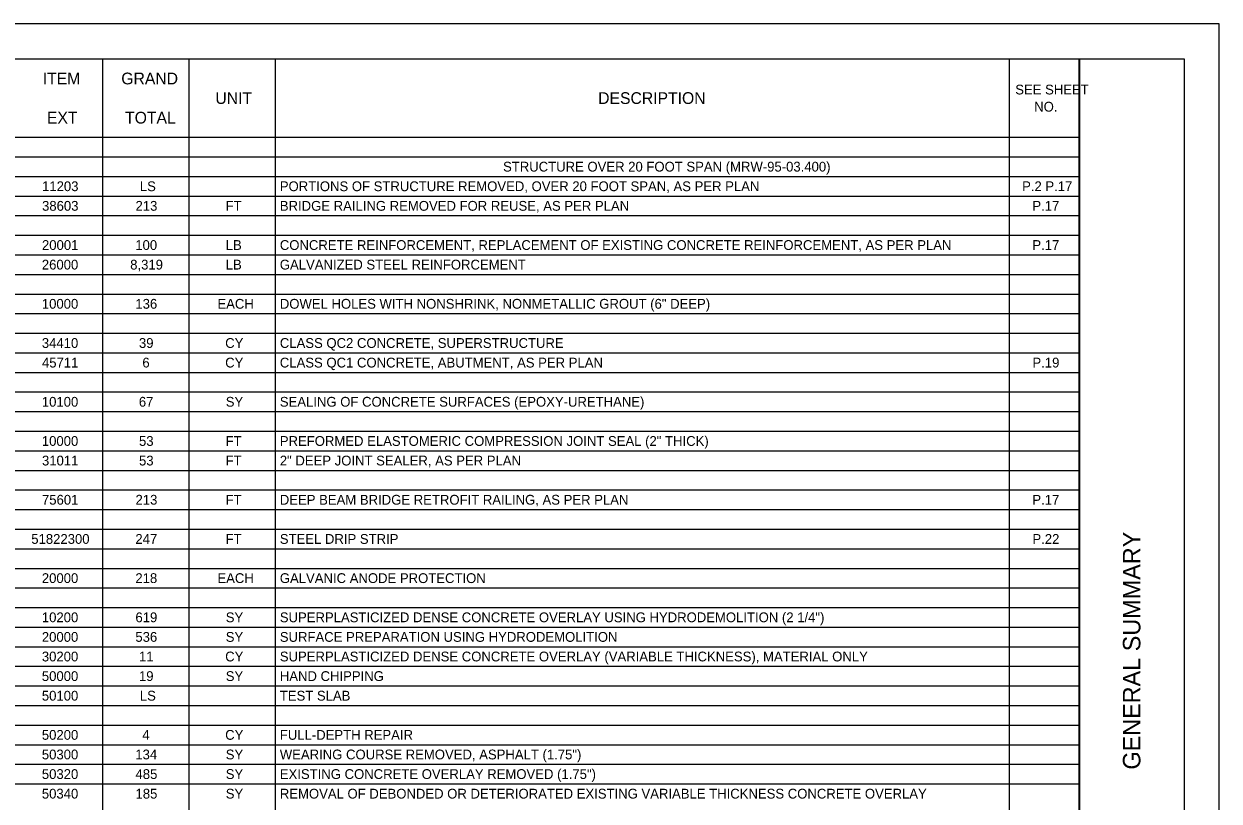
# Model space of a CAD drawing. Extents: x 0 to 34, y 0 to 22.
# Drawn here: x 16.91 to 34, y 10.89 to 22 of the extents above; entities that cross this region are included whole.
import ezdxf

# ---------------------------------------------------------------- set-up
doc = ezdxf.new("R2010")
doc.units = 0
for name, color, linetype in [('Default', 7, 'Continuous'), ('SH_Border', 7, 'Continuous'), ('SH_Cut_Line', 7, 'Continuous'), ('SH_Data', 7, 'Continuous')]:
    doc.layers.add(name, color=color, linetype=linetype)

msp = doc.modelspace()

# ---------------------------------------------------------------- linework, layer by layer
at = {"layer": 'SH_Border'}
msp.add_line((32, 0.5), (32, 21.5), dxfattribs=at)
msp.add_lwpolyline([(1.5, 21.5), (33.5, 21.5), (33.5, 0.5), (1.5, 0.5)], close=True, dxfattribs=at)
at = {"layer": 'SH_Cut_Line'}
msp.add_lwpolyline([(0, 0), (34, 0), (34, 22), (0, 22)], close=True, dxfattribs=at)
at = {"layer": 'SH_Data'}
for p, q in [((1.5, 21.5), (32.004, 21.5)), ((18.036, 21.5), (18.036, 0.5)), ((19.272, 21.5), (19.272, 0.5)), ((20.507, 21.5), (20.507, 0.5)), ((30.999, 21.5), (30.999, 0.5)), ((32.004, 21.5), (32.004, 0.5)), ((1.5, 20.38), (32.004, 20.38)), ((1.5, 20.1), (32.004, 20.1)), ((1.5, 19.82), (32.004, 19.82)), ((1.5, 19.54), (32.004, 19.54)), ((1.5, 19.26), (32.004, 19.26)), ((1.5, 18.98), (32.004, 18.98)), ((1.5, 18.7), (32.004, 18.7)), ((1.5, 18.42), (32.004, 18.42)), ((1.5, 18.14), (32.004, 18.14)), ((1.5, 17.86), (32.004, 17.86)), ((1.5, 17.58), (32.004, 17.58)), ((1.5, 17.3), (32.004, 17.3)), ((1.5, 17.02), (32.004, 17.02)), ((1.5, 16.74), (32.004, 16.74)), ((1.5, 16.46), (32.004, 16.46)), ((1.5, 16.18), (32.004, 16.18)), ((1.5, 15.9), (32.004, 15.9)), ((1.5, 15.62), (32.004, 15.62)), ((1.5, 15.34), (32.004, 15.34)), ((1.5, 15.06), (32.004, 15.06)), ((1.5, 14.78), (32.004, 14.78)), ((1.5, 14.5), (32.004, 14.5)), ((1.5, 14.22), (32.004, 14.22)), ((1.5, 13.94), (32.004, 13.94)), ((1.5, 13.66), (32.004, 13.66)), ((1.5, 13.38), (32.004, 13.38)), ((1.5, 13.1), (32.004, 13.1)), ((1.5, 12.82), (32.004, 12.82)), ((1.5, 12.54), (32.004, 12.54)), ((1.5, 12.26), (32.004, 12.26)), ((1.5, 11.98), (32.004, 11.98)), ((1.5, 11.7), (32.004, 11.7)), ((1.5, 11.42), (32.004, 11.42)), ((1.5, 11.14), (32.004, 11.14))]:
    msp.add_line(p, q, dxfattribs=at)

# ---------------------------------------------------------------- texts
at = {"layer": 'Default'}
for s, height, p in [('ITEM', 0.168, (17.184, 21.136)), ('GRAND', 0.168, (18.307, 21.136)), ('UNIT', 0.168, (19.652, 20.856)), ('DESCRIPTION', 0.168, (25.124, 20.856)), ('SEE SHEET ', 0.14, (31.086, 20.992)), ('NO.', 0.14, (31.357, 20.747)), ('EXT', 0.168, (17.244, 20.576)), ('TOTAL', 0.168, (18.361, 20.576)), ('STRUCTURE OVER 20 FOOT SPAN (MRW-95-03.400)', 0.14, (23.764, 19.89)), ('11203', 0.14, (17.174, 19.61)), ('LS', 0.14, (18.572, 19.61)), ('PORTIONS OF STRUCTURE REMOVED, OVER 20 FOOT SPAN, AS PER PLAN', 0.14, (20.573, 19.61)), ('P.2 P.17', 0.14, (31.184, 19.61)), ('38603', 0.14, (17.174, 19.33)), ('213', 0.14, (18.51, 19.33)), ('FT', 0.14, (19.797, 19.33)), ('BRIDGE RAILING REMOVED FOR REUSE, AS PER PLAN', 0.14, (20.573, 19.33)), ('P.17', 0.14, (31.331, 19.33)), ('20001', 0.14, (17.173, 18.77)), ('100', 0.14, (18.507, 18.77)), ('LB', 0.14, (19.8, 18.77)), ('CONCRETE REINFORCEMENT, REPLACEMENT OF EXISTING CONCRETE REINFORCEMENT, AS PER PLAN', 0.14, (20.573, 18.77)), ('P.17', 0.14, (31.331, 18.77)), ('26000', 0.14, (17.171, 18.49)), ('8,319', 0.14, (18.434, 18.49)), ('LB', 0.14, (19.8, 18.49)), ('GALVANIZED STEEL REINFORCEMENT', 0.14, (20.573, 18.49)), ('10000', 0.14, (17.171, 17.93)), ('136', 0.14, (18.508, 17.93)), ('EACH', 0.14, (19.681, 17.93)), ('DOWEL HOLES WITH NONSHRINK, NONMETALLIC GROUT (6" DEEP)', 0.14, (20.573, 17.93)), ('34410', 0.14, (17.171, 17.37)), ('39', 0.14, (18.559, 17.37)), ('CY', 0.14, (19.792, 17.37)), ('CLASS QC2 CONCRETE, SUPERSTRUCTURE', 0.14, (20.573, 17.37)), ('45711', 0.14, (17.173, 17.09)), ('6', 0.14, (18.608, 17.09)), ('CY', 0.14, (19.792, 17.09)), ('CLASS QC1 CONCRETE, ABUTMENT, AS PER PLAN', 0.14, (20.573, 17.09)), ('P.19', 0.14, (31.332, 17.09)), ('10100', 0.14, (17.171, 16.53)), ('67', 0.14, (18.558, 16.53)), ('SY', 0.14, (19.8, 16.53)), ('SEALING OF CONCRETE SURFACES (EPOXY-URETHANE)', 0.14, (20.573, 16.53)), ('10000', 0.14, (17.171, 15.97)), ('53', 0.14, (18.56, 15.97)), ('FT', 0.14, (19.797, 15.97)), ('PREFORMED ELASTOMERIC COMPRESSION JOINT SEAL (2" THICK)', 0.14, (20.573, 15.97)), ('31011', 0.14, (17.173, 15.69)), ('53', 0.14, (18.56, 15.69)), ('FT', 0.14, (19.797, 15.69)), ('2" DEEP JOINT SEALER, AS PER PLAN', 0.14, (20.573, 15.69)), ('75601', 0.14, (17.173, 15.13)), ('213', 0.14, (18.51, 15.13)), ('FT', 0.14, (19.797, 15.13)), ('DEEP BEAM BRIDGE RETROFIT RAILING, AS PER PLAN', 0.14, (20.573, 15.13)), ('P.17', 0.14, (31.331, 15.13)), ('51822300', 0.14, (17.02, 14.57)), ('247', 0.14, (18.508, 14.57)), ('FT', 0.14, (19.797, 14.57)), ('STEEL DRIP STRIP', 0.14, (20.573, 14.57)), ('P.22', 0.14, (31.332, 14.57)), ('20000', 0.14, (17.171, 14.01)), ('218', 0.14, (18.508, 14.01)), ('EACH', 0.14, (19.681, 14.01)), ('GALVANIC ANODE PROTECTION', 0.14, (20.573, 14.01)), ('10200', 0.14, (17.171, 13.45)), ('619', 0.14, (18.509, 13.45)), ('SY', 0.14, (19.8, 13.45)), ('SUPERPLASTICIZED DENSE CONCRETE OVERLAY USING HYDRODEMOLITION (2 1/4")', 0.14, (20.573, 13.45)), ('20000', 0.14, (17.171, 13.17)), ('536', 0.14, (18.508, 13.17)), ('SY', 0.14, (19.8, 13.17)), ('SURFACE PREPARATION USING HYDRODEMOLITION', 0.14, (20.573, 13.17)), ('30200', 0.14, (17.171, 12.89)), ('11', 0.14, (18.559, 12.89)), ('CY', 0.14, (19.792, 12.89)), ('SUPERPLASTICIZED DENSE CONCRETE OVERLAY (VARIABLE THICKNESS), MATERIAL ONLY', 0.14, (20.573, 12.89)), ('50000', 0.14, (17.171, 12.61)), ('19', 0.14, (18.559, 12.61)), ('SY', 0.14, (19.8, 12.61)), ('HAND CHIPPING', 0.14, (20.573, 12.61)), ('50100', 0.14, (17.171, 12.33)), ('LS', 0.14, (18.572, 12.33)), ('TEST SLAB', 0.14, (20.573, 12.33)), ('50200', 0.14, (17.171, 11.77)), ('4', 0.14, (18.607, 11.77)), ('CY', 0.14, (19.792, 11.77)), ('FULL-DEPTH REPAIR', 0.14, (20.573, 11.77)), ('50300', 0.14, (17.171, 11.49)), ('134', 0.14, (18.507, 11.49)), ('SY', 0.14, (19.8, 11.49)), ('WEARING COURSE REMOVED, ASPHALT (1.75")', 0.14, (20.573, 11.49)), ('50320', 0.14, (17.171, 11.21)), ('485', 0.14, (18.51, 11.21)), ('SY', 0.14, (19.8, 11.21)), ('EXISTING CONCRETE OVERLAY REMOVED (1.75")', 0.14, (20.573, 11.21)), ('50340', 0.14, (17.171, 10.93)), ('185', 0.14, (18.51, 10.93)), ('SY', 0.14, (19.8, 10.93)), ('REMOVAL OF DEBONDED OR DETERIORATED EXISTING VARIABLE THICKNESS CONCRETE OVERLAY', 0.14, (20.573, 10.93))]:
    msp.add_text(s, height=height, dxfattribs=at).set_placement(p)
at = {"layer": 'SH_Data'}
msp.add_text('GENERAL SUMMARY', height=0.25, rotation=90, dxfattribs=at).set_placement((32.875, 11.344))

doc.saveas('drawing.dxf')
